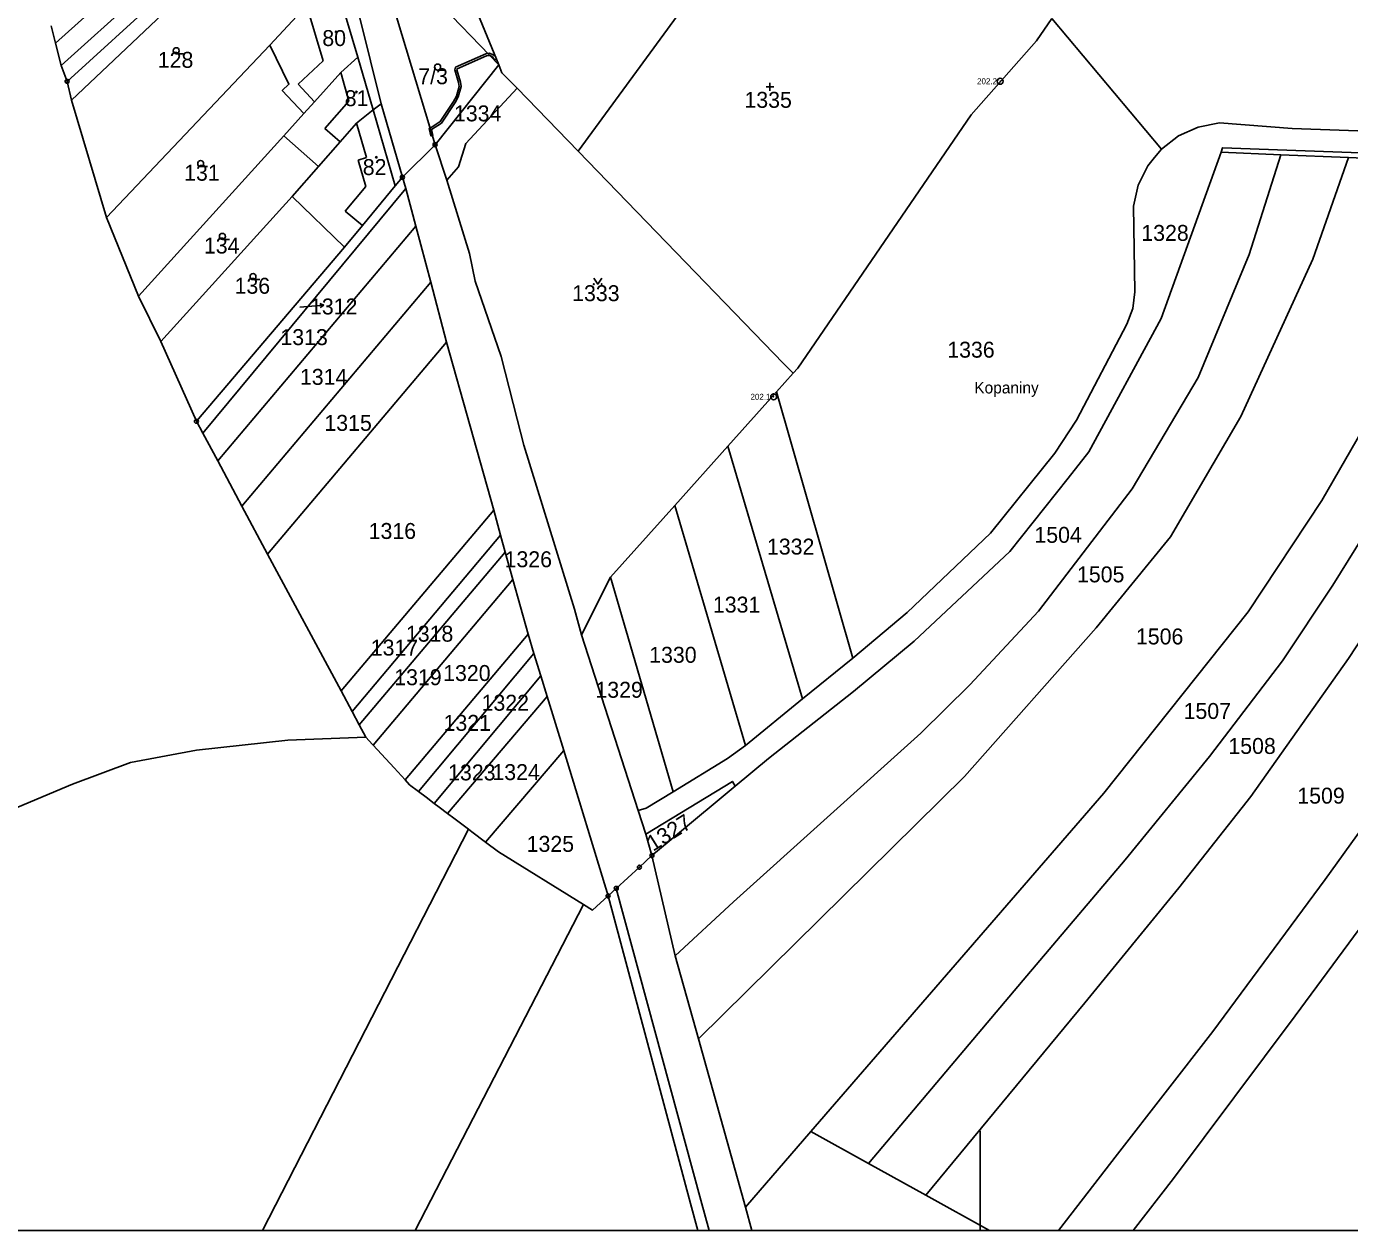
# Model space of a CAD drawing. Extents: x -564516 to -563466, y -1163913 to -1163170.
# Drawn here: x -564230.8 to -563898.7, y -1163912.5 to -1163610.3 of the extents above; entities that cross this region are included whole.
import ezdxf

# ---------------------------------------------------------------- set-up
doc = ezdxf.new("R2010")
doc.units = 0
for name, color, linetype in [('_parcely', 7, 'Continuous'), ('_parcely přehledka', 7, 'Continuous'), ('Hranice parcel', 7, 'Continuous'), ('Obvod PU', 7, 'Continuous'), ('Parcelní čísla', 7, 'Continuous'), ('Pop  PČ popisy', 7, 'Continuous'), ('Vnitřní kresba', 7, 'Continuous'), ('Věcná břemena k části', 7, 'Continuous'), ('Značky bodu BP', 7, 'Continuous'), ('Značky budov', 7, 'Continuous'), ('Značky kultur', 7, 'Continuous')]:
    doc.layers.add(name, color=color, linetype=linetype)

msp = doc.modelspace()

# ---------------------------------------------------------------- linework, layer by layer
at = {"layer": '_parcely'}
msp.add_line((-563991.35, -1163912.53), (-563991.35, -1163887.53), dxfattribs=at)
at = {"layer": '_parcely přehledka'}
msp.add_lwpolyline([(-564516.35, -1163170.03), (-564516.35, -1163912.53), (-563466.35, -1163912.53), (-563466.35, -1163170.03)], dxfattribs=at)
at = {"layer": 'Hranice parcel'}
for p, q in [((-564223.46, -1163614.55), (-564168.46, -1163564.89)), ((-564222.05, -1163620.11), (-564164.82, -1163568.62)), ((-564220.56, -1163624.11), (-564162.36, -1163571.14)), ((-564219.45, -1163628.81), (-564176.54, -1163588.25)), ((-564141.45, -1163589.58), (-564112.22, -1163619.96)), ((-564147.6, -1163618.07), (-564153.46, -1163598.26)), ((-564092.3, -1163641.63), (-564063.05, -1163601.67)), ((-564224.59, -1163610.2), (-564223.46, -1163614.55)), ((-564162.89, -1163607.78), (-564169.68, -1163615)), ((-563945.88, -1163641.11), (-563973.39, -1163608.38)), ((-564223.46, -1163614.55), (-564222.05, -1163620.11)), ((-564210.67, -1163658.27), (-564169.68, -1163615)), ((-564222.05, -1163620.11), (-564220.56, -1163624.11)), ((-564143.7, -1163631.27), (-564147.6, -1163618.07)), ((-564128.21, -1163640.02), (-564112.22, -1163619.96)), ((-564220.56, -1163624.11), (-564219.45, -1163628.81)), ((-564107.61, -1163625.85), (-564092.3, -1163641.63)), ((-564219.45, -1163628.81), (-564210.67, -1163658.27)), ((-564141.75, -1163629.73), (-564143.7, -1163631.27)), ((-564136.4, -1163648.2), (-564141.75, -1163629.73)), ((-564161.12, -1163632.21), (-564166.15, -1163637.81)), ((-564202.62, -1163678), (-564166.15, -1163637.81)), ((-564166.15, -1163637.81), (-564157.42, -1163645.45)), ((-564136.4, -1163648.2), (-564128.21, -1163640.02)), ((-564128.21, -1163640.02), (-564125.28, -1163648.88)), ((-563915.93, -1163642.54), (-563930.91, -1163641.92)), ((-563898.88, -1163643.25), (-563915.93, -1163642.54)), ((-563866.43, -1163644.59), (-563898.88, -1163643.25)), ((-564157.42, -1163645.45), (-564164.08, -1163653.05)), ((-564135.56, -1163651.03), (-564136.4, -1163648.2)), ((-564197.05, -1163689.43), (-564164.08, -1163653.05)), ((-564186.49, -1163712.43), (-564135.56, -1163651.03)), ((-564164.08, -1163653.05), (-564150.92, -1163665.7)), ((-564133.04, -1163660.47), (-564135.56, -1163651.03)), ((-564210.67, -1163658.27), (-564202.62, -1163678)), ((-564182.77, -1163719.37), (-564133.04, -1163660.47)), ((-564129.24, -1163674.51), (-564133.04, -1163660.47)), ((-564188.1, -1163709.43), (-564150.92, -1163665.7)), ((-564176.67, -1163730.73), (-564129.24, -1163674.51)), ((-564125.31, -1163689.57), (-564129.24, -1163674.51)), ((-564202.62, -1163678), (-564197.05, -1163689.43)), ((-564197.05, -1163689.43), (-564188.1, -1163709.43)), ((-564170.24, -1163742.74), (-564125.31, -1163689.57)), ((-564113.48, -1163731.73), (-564125.31, -1163689.57)), ((-564042.49, -1163702.03), (-564038.32, -1163697.37)), ((-564054.69, -1163715.66), (-564042.49, -1163702.03)), ((-564023.36, -1163768.85), (-564042.49, -1163702.03)), ((-564188.1, -1163709.43), (-564186.49, -1163712.43)), ((-564186.49, -1163712.43), (-564182.77, -1163719.37)), ((-564068.02, -1163730.56), (-564054.69, -1163715.66)), ((-564054.69, -1163715.66), (-564035.96, -1163779.13)), ((-564182.77, -1163719.37), (-564176.67, -1163730.73)), ((-564176.67, -1163730.73), (-564170.24, -1163742.74)), ((-564151.79, -1163777.11), (-564113.48, -1163731.73)), ((-564111.75, -1163738.01), (-564113.48, -1163731.73)), ((-564084.13, -1163748.56), (-564068.02, -1163730.56)), ((-564050.26, -1163790.8), (-564068.02, -1163730.56)), ((-564149.04, -1163782.26), (-564111.75, -1163738.01)), ((-564110.59, -1163742.26), (-564111.75, -1163738.01)), ((-564170.24, -1163742.74), (-564151.79, -1163777.11)), ((-564110.59, -1163742.26), (-564147.22, -1163785.64)), ((-564108.68, -1163749.18), (-564110.59, -1163742.26)), ((-564143.75, -1163790.7), (-564108.68, -1163749.18)), ((-564104.87, -1163762.87), (-564108.68, -1163749.18)), ((-564091.46, -1163763.02), (-564084.13, -1163748.56)), ((-564068.41, -1163802.44), (-564084.13, -1163748.56)), ((-564135.73, -1163799.43), (-564104.87, -1163762.87)), ((-564103.38, -1163767.72), (-564104.87, -1163762.87)), ((-564091.46, -1163763.02), (-564077.18, -1163807.12)), ((-564132.34, -1163802.38), (-564103.38, -1163767.72)), ((-564101.66, -1163773.32), (-564103.38, -1163767.72)), ((-564035.96, -1163779.13), (-564023.36, -1163768.85)), ((-564128.43, -1163805.33), (-564101.66, -1163773.32)), ((-564100.04, -1163778.49), (-564101.66, -1163773.32)), ((-564151.79, -1163777.11), (-564149.04, -1163782.26)), ((-564125.08, -1163807.86), (-564100.04, -1163778.49)), ((-564095.92, -1163792.07), (-564100.04, -1163778.49)), ((-564050.26, -1163790.8), (-564035.96, -1163779.13)), ((-564149.04, -1163782.26), (-564147.22, -1163785.64)), ((-564147.22, -1163785.64), (-564145.57, -1163788.72)), ((-564115.55, -1163815.06), (-564095.92, -1163792.07)), ((-564084.77, -1163828.54), (-564095.92, -1163792.07)), ((-564077.18, -1163807.12), (-564075.32, -1163813.06)), ((-564075.32, -1163813.06), (-564073.75, -1163818.41)), ((-564067.92, -1163843.63), (-564073.75, -1163818.41)), ((-564062.09, -1163864.39), (-564067.92, -1163843.63)), ((-564050.26, -1163906.68), (-564062.09, -1163864.39)), ((-564050.26, -1163906.68), (-564033.85, -1163887.71)), ((-564033.85, -1163887.71), (-564019.41, -1163895.71)), ((-564019.41, -1163895.71), (-564005.03, -1163903.67)), ((-564005.03, -1163903.67), (-563989.02, -1163912.53))]:
    msp.add_line(p, q, dxfattribs=at)
for points in [[(-564141.75, -1163629.73), (-564147.11, -1163608.19), (-564150.44, -1163590.7), (-564149.91, -1163571.99), (-564143.77, -1163544.97)], [(-564112.22, -1163619.96), (-564129.19, -1163578.66), (-564125.43, -1163565.71)], [(-564141.45, -1163589.58), (-564138.93, -1163604.36), (-564128.21, -1163640.02)], [(-564038.32, -1163697.37), (-564037.15, -1163696.07), (-563993.61, -1163632.54), (-563977.25, -1163613.92), (-563973.39, -1163608.38)], [(-564169.68, -1163615), (-564164.9, -1163624.84), (-564166.58, -1163626.42), (-564161.12, -1163632.21)], [(-564161.12, -1163632.21), (-564158.44, -1163629.22), (-564151.87, -1163621.91), (-564147.6, -1163618.07)], [(-564112.22, -1163619.96), (-564111.4, -1163621.95), (-564107.61, -1163625.85)], [(-564125.28, -1163648.88), (-564122.35, -1163645.58), (-564120.45, -1163639.74), (-564107.61, -1163625.85)], [(-564157.42, -1163645.45), (-564152.02, -1163639.28), (-564147.94, -1163634.62), (-564143.7, -1163631.27)], [(-563945.88, -1163641.11), (-563941.57, -1163637.81), (-563936.63, -1163635.58), (-563931.3, -1163634.54), (-563913.06, -1163635.92), (-563861.14, -1163637.78)], [(-564092.3, -1163641.63), (-564040.72, -1163694.91), (-564038.32, -1163697.37)], [(-564067.92, -1163843.63), (-564053.32, -1163830), (-564006.23, -1163787.74), (-563993.99, -1163775.6), (-563976.74, -1163757.12), (-563953.25, -1163726.38), (-563936.65, -1163698.43), (-563923.86, -1163667.53), (-563915.93, -1163642.54)], [(-564062.09, -1163864.39), (-563995.33, -1163798.54), (-563962.27, -1163761.24), (-563943.57, -1163738.41), (-563925.96, -1163708.23), (-563907.83, -1163668.76), (-563898.88, -1163643.25)], [(-564023.36, -1163768.85), (-564009.73, -1163757.43), (-563988.8, -1163737.54), (-563972.63, -1163717.42), (-563967.15, -1163709.12), (-563954.55, -1163685.04), (-563953.03, -1163681.15), (-563952.52, -1163676.96), (-563952.92, -1163655.47), (-563951.71, -1163650.18), (-563949.32, -1163645.31), (-563947.61, -1163643.22), (-563945.88, -1163641.11)], [(-564033.85, -1163887.71), (-563960.37, -1163802.77), (-563924.09, -1163757.23), (-563905.61, -1163729.28), (-563893.92, -1163709.01), (-563880, -1163679.45), (-563866.43, -1163644.59)], [(-564019.41, -1163895.71), (-563980.6, -1163849.7), (-563954.99, -1163819.51), (-563933.77, -1163793.6), (-563915.51, -1163769.54), (-563902.82, -1163750.6), (-563880.21, -1163714.08), (-563865.64, -1163681.81), (-563852.28, -1163645.65)], [(-564005.03, -1163903.67), (-563965.09, -1163855.39), (-563941.49, -1163826.5), (-563923.42, -1163803.62), (-563898.92, -1163768.98), (-563879.88, -1163739.93), (-563867.29, -1163716.65), (-563853.12, -1163688.16), (-563837.56, -1163646.83)], [(-564150.92, -1163665.7), (-564146.44, -1163660.3), (-564138.18, -1163650.34), (-564136.4, -1163648.2)], [(-564125.28, -1163648.88), (-564119.58, -1163667.35), (-564118.1, -1163674.3), (-564111.58, -1163693.21), (-564107.59, -1163708.92), (-564105.94, -1163715.39), (-564093.18, -1163756.62), (-564091.46, -1163763.02)], [(-563971.69, -1163912.53), (-563956.92, -1163893.35), (-563932.93, -1163862.62), (-563904.78, -1163824.4), (-563885.89, -1163798.15), (-563869.34, -1163772.9), (-563860.8, -1163759.16), (-563843.13, -1163727.45), (-563830.48, -1163702.96), (-563823.28, -1163687.14), (-563818.58, -1163675.31), (-563810.46, -1163651.3)], [(-563952.94, -1163912.53), (-563942.84, -1163899.5), (-563912.32, -1163858.67), (-563872.16, -1163804.24), (-563858.94, -1163783.59), (-563847.66, -1163765.02), (-563838.38, -1163748.17), (-563818.3, -1163711.53), (-563805.22, -1163681.25), (-563795.8, -1163653.08)], [(-564068.41, -1163802.44), (-564054.76, -1163794.08), (-564050.26, -1163790.8)], [(-564052.83, -1163800.98), (-564053.56, -1163799.83), (-564075.32, -1163813.06)], [(-564077.18, -1163807.12), (-564075.21, -1163806.57), (-564068.41, -1163802.44)], [(-564171.55, -1163912.53), (-564119.83, -1163811.83)], [(-564084.77, -1163828.54), (-564064.12, -1163905.73), (-564062.23, -1163912.53)], [(-564082.71, -1163826.65), (-564061.52, -1163904.92), (-564059.43, -1163912.53)], [(-564090.91, -1163830.72), (-564133.16, -1163912.53)], [(-564048.67, -1163912.53), (-564050.26, -1163906.68)]]:
    msp.add_lwpolyline(points, dxfattribs=at)
at = {"layer": 'Obvod PU'}
msp.add_line((-564082.71, -1163826.65), (-564084.77, -1163828.54), dxfattribs=at)
msp.add_line((-564082.71, -1163826.65), (-564084.77, -1163828.54), dxfattribs=at)
for points in [[(-563930.91, -1163641.92), (-563945.92, -1163683.61), (-563964.08, -1163717.1), (-563969.31, -1163723.74), (-563983.9, -1163742.07), (-564007.92, -1163764.64), (-564023.16, -1163777.23), (-564044.53, -1163794.09), (-564052.83, -1163800.98)], [(-563930.91, -1163641.92), (-563945.92, -1163683.61), (-563964.08, -1163717.1), (-563969.31, -1163723.74), (-563983.9, -1163742.07), (-564007.92, -1163764.64), (-564023.16, -1163777.23), (-564044.53, -1163794.09), (-564052.83, -1163800.98)], [(-563863.67, -1163643.2), (-563930.57, -1163640.78), (-563930.91, -1163641.92)], [(-563863.67, -1163643.2), (-563930.57, -1163640.78), (-563930.91, -1163641.92)], [(-564145.57, -1163788.72), (-564165.13, -1163789.46), (-564188.06, -1163792), (-564204.66, -1163795.09), (-564219.21, -1163800.53), (-564275.9, -1163824.32), (-564309.77, -1163843.83), (-564359.7, -1163877.05), (-564371.94, -1163888.45), (-564374.47, -1163874.66), (-564375.88, -1163841.01), (-564379.57, -1163838.23)], [(-564145.57, -1163788.72), (-564165.13, -1163789.46), (-564188.06, -1163792), (-564204.66, -1163795.09), (-564219.21, -1163800.53), (-564275.9, -1163824.32), (-564309.77, -1163843.83), (-564359.7, -1163877.05), (-564371.94, -1163888.45), (-564374.47, -1163874.66), (-564375.88, -1163841.01), (-564379.57, -1163838.23)], [(-564143.75, -1163790.7), (-564143.87, -1163790.57), (-564145.57, -1163788.72)], [(-564143.75, -1163790.7), (-564143.87, -1163790.57), (-564145.57, -1163788.72)], [(-564135.73, -1163799.43), (-564138.49, -1163796.43), (-564141.64, -1163793), (-564143.75, -1163790.7)], [(-564135.73, -1163799.43), (-564138.49, -1163796.43), (-564141.64, -1163793), (-564143.75, -1163790.7)], [(-564132.34, -1163802.38), (-564134.59, -1163800.68), (-564135.73, -1163799.43)], [(-564132.34, -1163802.38), (-564134.59, -1163800.68), (-564135.73, -1163799.43)], [(-564128.43, -1163805.33), (-564130.46, -1163803.8), (-564132.34, -1163802.38)], [(-564128.43, -1163805.33), (-564130.46, -1163803.8), (-564132.34, -1163802.38)], [(-564052.83, -1163800.98), (-564067.88, -1163813.47), (-564069.41, -1163814.81), (-564073.75, -1163818.41)], [(-564052.83, -1163800.98), (-564067.88, -1163813.47), (-564069.41, -1163814.81), (-564073.75, -1163818.41)], [(-564125.08, -1163807.86), (-564127.17, -1163806.28), (-564128.43, -1163805.33)], [(-564125.08, -1163807.86), (-564127.17, -1163806.28), (-564128.43, -1163805.33)], [(-564119.83, -1163811.83), (-564123.49, -1163809.06), (-564125.08, -1163807.86)], [(-564119.83, -1163811.83), (-564123.49, -1163809.06), (-564125.08, -1163807.86)], [(-564115.55, -1163815.06), (-564119, -1163812.46), (-564119.83, -1163811.83)], [(-564115.55, -1163815.06), (-564119, -1163812.46), (-564119.83, -1163811.83)], [(-564090.91, -1163830.72), (-564112.29, -1163817.52), (-564115.55, -1163815.06)], [(-564090.91, -1163830.72), (-564112.29, -1163817.52), (-564115.55, -1163815.06)], [(-564073.75, -1163818.41), (-564076.9, -1163821.34), (-564082.71, -1163826.65)], [(-564073.75, -1163818.41), (-564076.9, -1163821.34), (-564082.71, -1163826.65)], [(-564084.77, -1163828.54), (-564088.67, -1163832.11), (-564090.91, -1163830.72)], [(-564084.77, -1163828.54), (-564088.67, -1163832.11), (-564090.91, -1163830.72)]]:
    msp.add_lwpolyline(points, dxfattribs=at)
at = {"layer": 'Pop  PČ popisy'}
for p, q in [((-564159.11, -1163680.51), (-564156.12, -1163680.25)), ((-564156.12, -1163680.25), (-564157.16, -1163679.84)), ((-564156.12, -1163680.25), (-564157.07, -1163680.84)), ((-564162.18, -1163680.77), (-564159.11, -1163680.51))]:
    msp.add_line(p, q, dxfattribs=at)
at = {"layer": 'Vnitřní kresba'}
for p, q in [((-564160.37, -1163605.23), (-564156.31, -1163618.94)), ((-564156.31, -1163618.94), (-564162.57, -1163624.84)), ((-564149.84, -1163629.05), (-564151.87, -1163621.91)), ((-564158.44, -1163629.22), (-564162.57, -1163624.84)), ((-564149.84, -1163629.05), (-564155.86, -1163635.92)), ((-564138.18, -1163650.34), (-564143.7, -1163631.27)), ((-564155.86, -1163635.92), (-564152.02, -1163639.28)), ((-564145.43, -1163643.26), (-564147.94, -1163634.62)), ((-564145.43, -1163643.26), (-564147.5, -1163643.86)), ((-564147.5, -1163643.86), (-564145.58, -1163650.49)), ((-564150.75, -1163656.72), (-564145.58, -1163650.49)), ((-564150.75, -1163656.72), (-564146.44, -1163660.3))]:
    msp.add_line(p, q, dxfattribs=at)
at = {"layer": 'Věcná břemena k části'}
msp.add_lwpolyline([(-564129.09, -1163636.18), (-564126.56, -1163634.59), (-564123.17, -1163629.45), (-564122.4, -1163628.02), (-564121.66, -1163625.41), (-564121.8, -1163624.29), (-564122.71, -1163621.24), (-564122.63, -1163620.95), (-564115.3, -1163617.69), (-564114.43, -1163617.66), (-564113.85, -1163617.89), (-564113.13, -1163618.68), (-564112.79, -1163618.58), (-564113.13, -1163617.74), (-564113.27, -1163617.78), (-564113.55, -1163617.47), (-564114.58, -1163617.06), (-564114.95, -1163617.12), (-564115.44, -1163617.21), (-564123.05, -1163620.59), (-564123.23, -1163621.24), (-564122.3, -1163624.39), (-564122.16, -1163625.37), (-564122.86, -1163627.84), (-564123.59, -1163629.19), (-564126.92, -1163634.23), (-564129.47, -1163635.83), (-564129.65, -1163635.94), (-564129.26, -1163637.8), (-564128.9, -1163637.72), (-564128.77, -1163637.69)], close=True, dxfattribs=at)
at = {"layer": 'Značky bodu BP'}
for centre, radius in [((-564220.56, -1163624.11), 0.5), ((-563986.34, -1163624.09), 0.75), ((-564220.56, -1163624.11), 0.0303), ((-563986.34, -1163624.09), 0.03), ((-564128.21, -1163640.02), 0.5), ((-564128.21, -1163640.02), 0.0303), ((-564136.4, -1163648.2), 0.5), ((-564136.4, -1163648.2), 0.0303), ((-564043.21, -1163703.28), 0.75), ((-564043.21, -1163703.28), 0.03), ((-564188.1, -1163709.43), 0.5), ((-564188.1, -1163709.43), 0.0303), ((-564073.75, -1163818.41), 0.5), ((-564073.75, -1163818.41), 0.0303), ((-564076.9, -1163821.34), 0.5), ((-564076.9, -1163821.34), 0.0303), ((-564082.71, -1163826.65), 0.5), ((-564082.71, -1163826.65), 0.0303), ((-564084.77, -1163828.54), 0.5), ((-564084.77, -1163828.54), 0.0303)]:
    msp.add_circle(centre, radius, dxfattribs=at)
at = {"layer": 'Značky budov'}
for centre in [(-564153.05, -1163611.7), (-564147.94, -1163626.79), (-564142.94, -1163643.16)]:
    msp.add_circle(centre, 0.175, dxfattribs=at)
at = {"layer": 'Značky kultur'}
for p, q in [((-564193.17, -1163617.17), (-564191.42, -1163617.17)), ((-564127.56, -1163621.28), (-564125.81, -1163621.28)), ((-564043.13, -1163625.48), (-564045.13, -1163625.48)), ((-564044.13, -1163626.48), (-564044.13, -1163624.48)), ((-564187.04, -1163645.5), (-564185.29, -1163645.5)), ((-564181.59, -1163663.77), (-564179.84, -1163663.77)), ((-564173.9, -1163673.87), (-564172.15, -1163673.87))]:
    msp.add_line(p, q, dxfattribs=at)
msp.add_lwpolyline([(-564088.37, -1163673.51), (-564087.37, -1163675.01), (-564086.37, -1163673.51)], dxfattribs=at)
for centre, radius in [((-564193.17, -1163616.42), 0.75), ((-564127.56, -1163620.53), 0.75), ((-564187.04, -1163644.75), 0.75), ((-564181.59, -1163663.02), 0.75), ((-564173.9, -1163673.12), 0.75), ((-564088.37, -1163675.01), 0.1), ((-564086.37, -1163675.01), 0.1)]:
    msp.add_circle(centre, radius, dxfattribs=at)

# ---------------------------------------------------------------- texts
at = {"layer": 'Parcelní čísla'}
for s, p in [('80', (-564156.5, -1163615.25)), ('128', (-564197.8, -1163620.72)), ('7/3', (-564132.41, -1163624.83)), ('81', (-564150.88, -1163630.34)), ('1335', (-564050.54, -1163630.75)), ('1334', (-564123.46, -1163634.15)), ('82', (-564146.35, -1163647.63)), ('131', (-564191.19, -1163649.05)), ('1328', (-563950.92, -1163664.15)), ('134', (-564186.22, -1163667.32)), ('136', (-564178.53, -1163677.42)), ('1333', (-564093.79, -1163679.28)), ('1312', (-564159.59, -1163682.62)), ('1313', (-564167.02, -1163690.31)), ('1336', (-563999.63, -1163693.46)), ('1314', (-564162.12, -1163700.28)), ('1315', (-564155.98, -1163711.83)), ('1316', (-564144.87, -1163738.96)), ('1504', (-563977.76, -1163739.93)), ('1332', (-564044.89, -1163742.88)), ('1326', (-564110.75, -1163746.06)), ('1505', (-563967.06, -1163749.85)), ('1331', (-564058.46, -1163757.44)), ('1318', (-564135.52, -1163764.74)), ('1506', (-563952.27, -1163765.43)), ('1317', (-564144.34, -1163768.23)), ('1330', (-564074.45, -1163770.04)), ('1319', (-564138.45, -1163775.66)), ('1320', (-564126.17, -1163774.61)), ('1329', (-564087.95, -1163778.82)), ('1322', (-564116.53, -1163782.07)), ('1507', (-563940.31, -1163784.14)), ('1321', (-564126.07, -1163787.12)), ('1508', (-563929.07, -1163792.92)), ('1323', (-564124.93, -1163799.56)), ('1324', (-564113.81, -1163799.48)), ('1509', (-563911.76, -1163805.39)), ('1325', (-564105.21, -1163817.49))]:
    msp.add_text(s, height=4, dxfattribs=at).set_placement(p)
msp.add_text('1327', height=4, rotation=32, dxfattribs=at).set_placement((-564073.49, -1163817.5))
at = {"layer": 'Pop  PČ popisy'}
msp.add_text('Kopaniny', height=2.9, dxfattribs=at).set_placement((-563992.84, -1163702.44))
at = {"layer": 'Značky bodu BP'}
for s, p in [('202.2', (-563992.16, -1163624.84)), ('202.1', (-564049.03, -1163704.03))]:
    msp.add_text(s, height=1.5, dxfattribs=at).set_placement(p)

doc.saveas('drawing.dxf')
